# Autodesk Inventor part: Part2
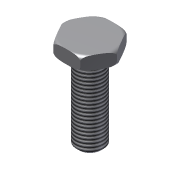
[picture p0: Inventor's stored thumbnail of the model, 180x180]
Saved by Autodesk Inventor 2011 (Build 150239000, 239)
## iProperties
Shininess: 77.0
Angle Display Precision: 2
Document Length Units: 11269
Document Angle Units: 11279
Document Time Units: 11290
Document Mass Units: 11283
Document Length Units Precision: 3
Document Angle Units Precision: 2
Created: 2002-01
Part Number: Part2
Document SubType Name: Modeling
Designer: ***
Density: 1 g/cm^3
Density: 0.0
Volumn: 0.0
Area: 0.0
PropertySet Name: Model Information
Control State: 0
Master: False
Checked Out: False
Author: ***
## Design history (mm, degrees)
sketch "Sketch1"
  geometry: C1 r 20 at (0, 0)
  constraints: 1 centre point
  dimensions: "d0" = 40 diameter of C1
extrude "Extrusion1" new body sketch "Sketch1" distance "d1" = 10; taper "d2" = 0 deg
fillet "Fillet1" dims "d3" = 3
sketch "Sketch3"
  geometry: L1 (20, 0)-(10, -17.321); L2 (10, -17.321)-(-10, -17.321); L3 (-10, -17.321)-(-20, 0); L4 (-20, 0)-(-10, 17.321); L5 (-10, 17.321)-(10, 17.321); L6 (10, 17.321)-(20, 0); C1 r 17 at (0, 0) reference; 1 further point
  constraints: 12 end point, 1 coincident, 11 other
extrude "Extrusion3" sketch "Sketch3" distance "d7" = 10; taper "d8" = 0 deg
sketch "Sketch2"
  geometry: C1 r 10 at (0, 0); 1 further point
  constraints: 1 centre point, 1 coincident
  dimensions: "d4" = 20 diameter of C1
extrude "Extrusion2" join sketch "Sketch2" distance "d5" = 60; taper "d6" = 0 deg
chamfer "Chamfer1" distance "d9" = 2; stored, may be unused: second distance "d10" = 2, angle "d13" = 45 deg
thread "Thread1" dims "d11" = 10, "d12" = 0
body "Solid1"
